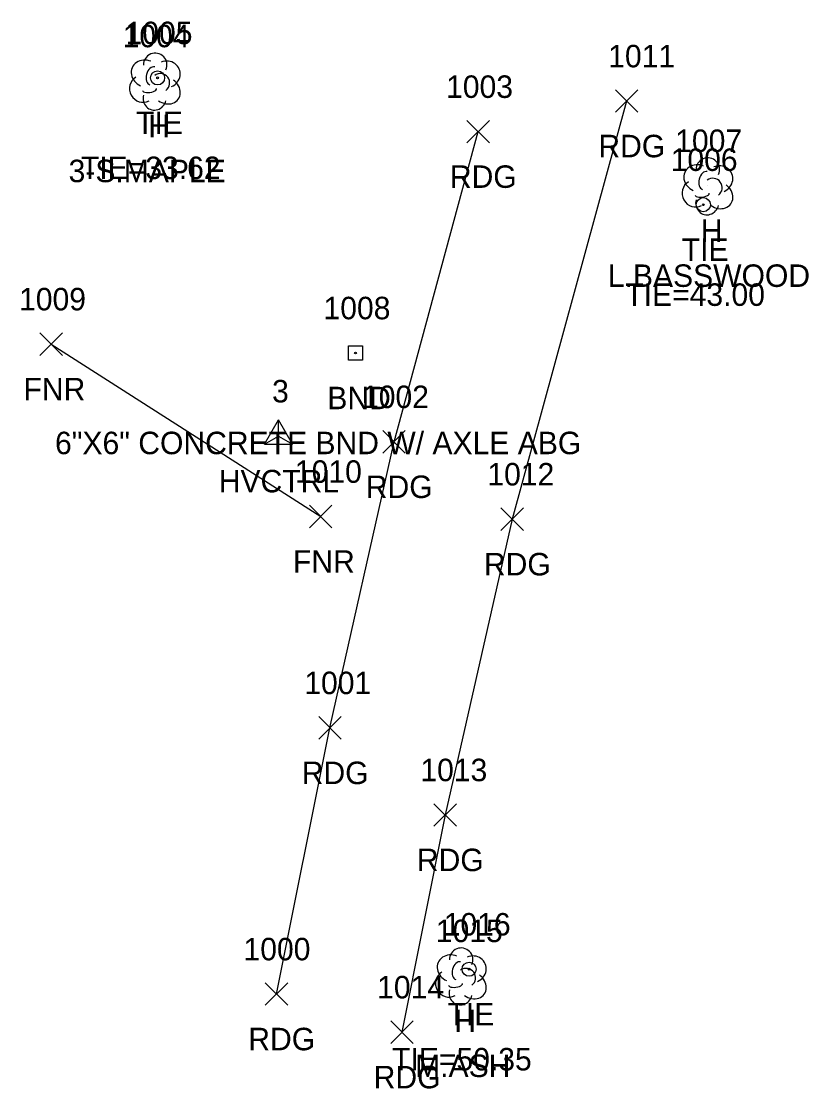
# Model space of a CAD drawing. Extents: x 1441651 to 1442140, y 243798 to 245625.
# Drawn here: x 1441782.2 to 1441852.2, y 244540.7 to 244635.6 of the extents above; entities that cross this region are included whole.
import ezdxf

# ---------------------------------------------------------------- set-up
doc = ezdxf.new("R2010")
doc.units = 0
for name, color, linetype in [('C_A', 7, 'Continuous'), ('C_C', 7, 'Continuous'), ('C_I', 7, 'Continuous'), ('CBP', 7, 'Continuous'), ('CPSM', 7, 'Continuous'), ('L_A', 7, 'Continuous'), ('L_C', 7, 'Continuous'), ('L_I', 7, 'Continuous'), ('L_TIC', 7, 'Continuous'), ('LFNC', 7, 'Continuous'), ('LTD', 7, 'Continuous'), ('M_A', 7, 'Continuous'), ('M_C', 7, 'Continuous'), ('M_I', 7, 'Continuous'), ('MHBP', 7, 'Continuous'), ('P_A', 7, 'Continuous'), ('P_I', 7, 'Continuous'), ('P_TIC', 7, 'Continuous'), ('PEU', 7, 'Continuous')]:
    doc.layers.add(name, color=color, linetype=linetype)

msp = doc.modelspace()

# ---------------------------------------------------------------- linework, layer by layer
at = {"layer": 'CBP'}
for centre, radius in [((1441794.348, 244630.614), 0.625), ((1441794.348, 244630.614), 0.0833), ((1441842.859, 244619.338), 0.625), ((1441842.859, 244619.338), 0.0833), ((1441822.038, 244551.338), 0.625), ((1441822.038, 244551.338), 0.0833)]:
    msp.add_circle(centre, radius, dxfattribs=at)
at = {"layer": 'CPSM'}
for p, q in [((1441803.84, 244598.031), (1441805.09, 244600.196)), ((1441806.34, 244598.031), (1441805.09, 244600.196)), ((1441805.09, 244598.752), (1441805.09, 244600.196)), ((1441803.84, 244598.031), (1441805.09, 244598.752)), ((1441805.09, 244598.752), (1441805.09, 244598.752)), ((1441805.09, 244598.752), (1441806.34, 244598.031)), ((1441803.84, 244598.031), (1441806.34, 244598.031))]:
    msp.add_line(p, q, dxfattribs=at)
at = {"layer": 'L_TIC'}
for points in [[(1441783.889, 244605.938), (1441785.889, 244607.938)], [(1441785.889, 244605.938), (1441783.889, 244607.938)], [(1441807.844, 244590.6), (1441809.844, 244592.6)], [(1441809.844, 244590.6), (1441807.844, 244592.6)]]:
    msp.add_lwpolyline(points, dxfattribs=at)
at = {"layer": 'LFNC'}
msp.add_lwpolyline([(1441784.889, 244606.938), (1441808.844, 244591.6)], dxfattribs=at)
at = {"layer": 'LTD'}
for p, q in [((1441794.086, 244630.339), (1441794.086, 244630.339)), ((1441794.086, 244630.339), (1441794.086, 244630.339)), ((1441843.209, 244621.026), (1441843.209, 244621.026)), ((1441843.209, 244621.026), (1441843.209, 244621.026)), ((1441821.286, 244550.751), (1441821.286, 244550.751)), ((1441821.286, 244550.751), (1441821.286, 244550.751))]:
    msp.add_line(p, q, dxfattribs=at)
for centre in [(1441794.132, 244631.773), (1441843.256, 244622.46), (1441821.333, 244552.185)]:
    msp.add_arc(centre, 1.047, 335.52715, 180.95627, dxfattribs=at)
for centre, major_axis, ratio, start_param, end_param in [((1441793.294, 244631.005), (1.21, -0.512), 0.895232, 1.570796, 4.712389), ((1441793.877, 244630.797), (-0.208, -0.792), 0.645439, 3.141593, 6.283185), ((1441795.127, 244630.922), (-1.141, -0.483), 0.949671, 1.570796, 4.712389), ((1441794.586, 244630.172), (-0.5, 0.667), 0.989748, 3.141593, 6.283185), ((1441793.002, 244629.63), (0.584, -1.042), 0.959034, 3.141593, 6.283185), ((1441795.086, 244629.505), (-1.09, 0.792), 0.841452, 1.570796, 4.712389), ((1441794.086, 244628.839), (0.265, 1.061), 0.942809, 1.570796, 4.712389), ((1441793.627, 244629.589), (-0.625, -0.083), 0.423636, 0, 3.141593), ((1441842.417, 244621.692), (1.21, -0.512), 0.895232, 1.570796, 4.712389), ((1441843.001, 244621.484), (-0.208, -0.792), 0.645439, 3.141593, 6.283185), ((1441844.251, 244621.609), (-1.141, -0.483), 0.949671, 1.570796, 4.712389), ((1441842.126, 244620.317), (0.584, -1.042), 0.959034, 3.141593, 6.283185), ((1441843.709, 244620.859), (-0.5, 0.667), 0.989748, 3.141593, 6.283185), ((1441842.751, 244620.276), (-0.625, -0.083), 0.423636, 0, 3.141593), ((1441844.209, 244620.193), (-1.09, 0.792), 0.841452, 1.570796, 4.712389), ((1441843.21, 244619.526), (0.265, 1.061), 0.942809, 1.570796, 4.712389), ((1441820.494, 244551.417), (1.21, -0.512), 0.895232, 1.570796, 4.712389), ((1441821.078, 244551.209), (-0.208, -0.792), 0.645439, 3.141593, 6.283185), ((1441822.328, 244551.334), (-1.141, -0.483), 0.949671, 1.570796, 4.712389), ((1441820.203, 244550.042), (0.584, -1.042), 0.959034, 3.141593, 6.283185), ((1441821.786, 244550.584), (-0.5, 0.667), 0.989748, 3.141593, 6.283185), ((1441820.828, 244550.001), (-0.625, -0.083), 0.423636, 0, 3.141593), ((1441822.286, 244549.918), (-1.09, 0.792), 0.841452, 1.570796, 4.712389), ((1441821.286, 244549.251), (0.265, 1.061), 0.942809, 1.570796, 4.712389)]:
    msp.add_ellipse(centre, major_axis=major_axis, ratio=ratio, start_param=start_param, end_param=end_param, dxfattribs=at)
at = {"layer": 'MHBP'}
msp.add_lwpolyline([(1441811.32, 244606.772), (1441812.57, 244606.772), (1441812.57, 244605.522), (1441811.32, 244605.522)], close=True, dxfattribs=at)
msp.add_circle((1441811.945, 244606.147), 0.0833, dxfattribs=at)
at = {"layer": 'P_TIC'}
for points in [[(1441835.041, 244627.554), (1441837.041, 244629.554)], [(1441837.041, 244627.554), (1441835.041, 244629.554)], [(1441821.84, 244624.834), (1441823.84, 244626.834)], [(1441823.84, 244624.834), (1441821.84, 244626.834)], [(1441814.366, 244597.248), (1441816.366, 244599.248)], [(1441816.366, 244597.248), (1441814.366, 244599.248)], [(1441824.865, 244590.365), (1441826.865, 244592.365)], [(1441826.865, 244590.365), (1441824.865, 244592.365)], [(1441808.67, 244571.805), (1441810.67, 244573.805)], [(1441810.67, 244571.805), (1441808.67, 244573.805)], [(1441818.907, 244564.063), (1441820.907, 244566.063)], [(1441820.907, 244564.063), (1441818.907, 244566.063)], [(1441803.92, 244548.132), (1441805.92, 244550.132)], [(1441805.92, 244548.132), (1441803.92, 244550.132)], [(1441815.067, 244544.747), (1441817.067, 244546.747)], [(1441817.067, 244544.747), (1441815.067, 244546.747)]]:
    msp.add_lwpolyline(points, dxfattribs=at)
at = {"layer": 'PEU'}
for points in [[(1441836.041, 244628.554), (1441825.865, 244591.365), (1441819.907, 244565.063), (1441816.067, 244545.747)], [(1441804.92, 244549.132), (1441809.67, 244572.805), (1441815.366, 244598.248), (1441822.84, 244625.834)]]:
    msp.add_lwpolyline(points, dxfattribs=at)

# ---------------------------------------------------------------- texts
at = {"layer": 'C_A'}
for s, p in [('TIE', (1441792.427, 244625.614)), ('TIE', (1441840.938, 244614.338)), ('HVCTRL', (1441799.783, 244593.752)), ('TIE', (1441820.117, 244546.338))]:
    msp.add_text(s, height=2, dxfattribs=at).set_placement(p)
at = {"layer": 'C_C'}
for s, p in [('TIE=33.62', (1441787.529, 244621.614)), ('TIE=43.00', (1441835.922, 244610.338)), ('TIE=50.35', (1441815.188, 244542.338))]:
    msp.add_text(s, height=2, dxfattribs=at).set_placement(p)
at = {"layer": 'C_I'}
for s, p in [('1005', (1441791.497, 244633.614)), ('1006', (1441839.954, 244622.338)), ('3', (1441804.523, 244601.752)), ('1016', (1441819.778, 244554.338))]:
    msp.add_text(s, height=2, dxfattribs=at).set_placement(p)
at = {"layer": 'L_A'}
for s, p in [('H', (1441793.519, 244625.339)), ('H', (1441842.642, 244616.026)), ('FNR', (1441782.424, 244601.938)), ('FNR', (1441806.38, 244586.6)), ('H', (1441820.719, 244545.751))]:
    msp.add_text(s, height=2, dxfattribs=at).set_placement(p)
at = {"layer": 'L_C'}
for s, p in [('3-S.MAPLE', (1441786.432, 244621.339)), ('L.BASSWOOD', (1441834.367, 244612.026)), ('M.ASH', (1441817.239, 244541.751))]:
    msp.add_text(s, height=2, dxfattribs=at).set_placement(p)
at = {"layer": 'L_I'}
for s, p in [('1004', (1441791.235, 244633.339)), ('1007', (1441840.359, 244624.026)), ('1009', (1441782.03, 244609.938)), ('1010', (1441806.553, 244594.6)), ('1015', (1441819.081, 244553.751))]:
    msp.add_text(s, height=2, dxfattribs=at).set_placement(p)
at = {"layer": 'M_A'}
msp.add_text('BND', height=2, dxfattribs=at).set_placement((1441809.433, 244601.147))
at = {"layer": 'M_C'}
msp.add_text('6"X6" CONCRETE BND W/ AXLE ABG', height=2, dxfattribs=at).set_placement((1441785.228, 244597.147))
at = {"layer": 'M_I'}
msp.add_text('1008', height=2, dxfattribs=at).set_placement((1441809.094, 244609.147))
at = {"layer": 'P_A'}
for p in [(1441833.529, 244623.554), (1441820.328, 244620.834), (1441812.854, 244593.248), (1441823.353, 244586.365), (1441807.158, 244567.805), (1441817.395, 244560.063), (1441802.408, 244544.132), (1441813.555, 244540.747)]:
    msp.add_text('RDG', height=2, dxfattribs=at).set_placement(p)
at = {"layer": 'P_I'}
for s, p in [('1011', (1441834.403, 244631.554)), ('1003', (1441819.99, 244628.834)), ('1002', (1441812.516, 244601.248)), ('1012', (1441823.66, 244594.365)), ('1001', (1441807.386, 244575.805)), ('1013', (1441817.703, 244568.063)), ('1000', (1441801.983, 244552.132)), ('1014', (1441813.862, 244548.747))]:
    msp.add_text(s, height=2, dxfattribs=at).set_placement(p)

doc.saveas('drawing.dxf')
